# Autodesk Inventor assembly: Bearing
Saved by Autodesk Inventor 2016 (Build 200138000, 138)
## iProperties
Created: 2015-08
Part Number: Bearing
Document SubType Name: Assembly
Designer: Ugljesa
ClientObjectVersion: 1
Author: Ugljesa
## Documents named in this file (2)
- C:\Users\Ugljesa\Desktop\Turbokompr\Assembly1\Design Accelerator\Bearing2.iam
- C:\Users\Ugljesa\Documents\Inventor\Content Center Files\R2016\en-US\BS 292 (V)\BS 292_ Part 1 - N 1005 - 25 x 47 x 12.ipt
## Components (1 placed, 1 different names)
1. BS 292: Part 1 (V) (Metric) N 1005 - 25 x 47 x 12:1
